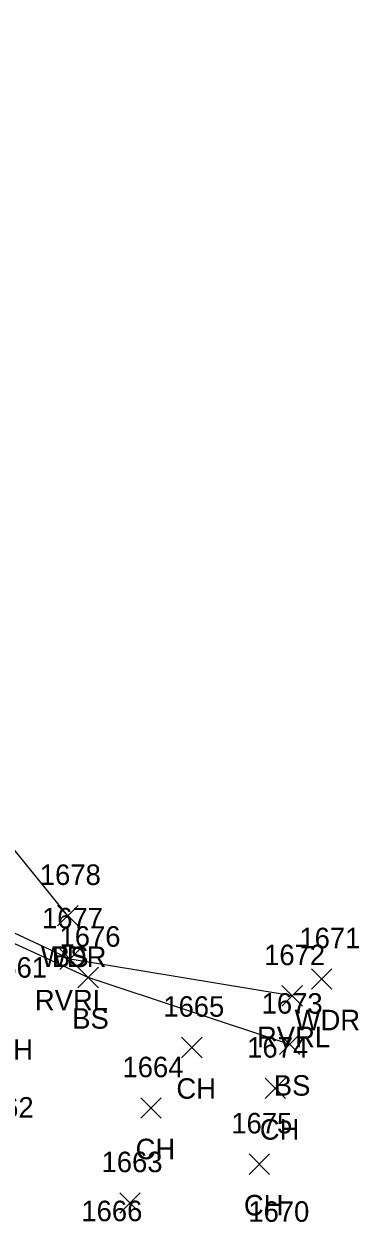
# Model space of a CAD drawing. Extents: x 1537342 to 1542195, y 163002 to 168596.
# Drawn here: x 1541938.8 to 1541971.5, y 163352.8 to 163469.6 of the extents above; entities that cross this region are included whole.
import ezdxf

# ---------------------------------------------------------------- set-up
doc = ezdxf.new("R2010")
doc.units = 0
for name, color, linetype in [('L_A', 7, 'Continuous'), ('L_I', 7, 'Continuous'), ('L_TIC', 7, 'Continuous'), ('LAWE', 7, 'Continuous'), ('LELB', 7, 'Continuous')]:
    doc.layers.add(name, color=color, linetype=linetype)

msp = doc.modelspace()

# ---------------------------------------------------------------- linework, layer by layer
at = {"layer": 'L_TIC'}
for points in [[(1541942.1, 163381.66), (1541944.1, 163383.66)], [(1541944.1, 163381.66), (1541942.1, 163383.66)], [(1541942.1, 163381.66), (1541944.1, 163383.66)], [(1541944.1, 163381.66), (1541942.1, 163383.66)], [(1541942.31, 163377.43), (1541944.31, 163379.43)], [(1541944.31, 163377.43), (1541942.31, 163379.43)], [(1541944.07, 163375.64), (1541946.07, 163377.64)], [(1541946.07, 163375.64), (1541944.07, 163377.64)], [(1541966.84, 163375.49), (1541968.84, 163377.49)], [(1541968.84, 163375.49), (1541966.84, 163377.49)], [(1541963.97, 163373.84), (1541965.97, 163375.84)], [(1541965.97, 163373.84), (1541963.97, 163375.84)], [(1541963.73, 163369.11), (1541965.73, 163371.11)], [(1541965.73, 163369.11), (1541963.73, 163371.11)], [(1541954.19, 163368.81), (1541956.19, 163370.81)], [(1541956.19, 163368.81), (1541954.19, 163370.81)], [(1541962.32, 163364.82), (1541964.32, 163366.82)], [(1541964.32, 163364.82), (1541962.32, 163366.82)], [(1541950.21, 163362.91), (1541952.21, 163364.91)], [(1541952.21, 163362.91), (1541950.21, 163364.91)], [(1541960.77, 163357.43), (1541962.77, 163359.43)], [(1541962.77, 163357.43), (1541960.77, 163359.43)], [(1541948.16, 163353.65), (1541950.16, 163355.65)], [(1541950.16, 163353.65), (1541948.16, 163355.65)]]:
    msp.add_lwpolyline(points, dxfattribs=at)
at = {"layer": 'LAWE'}
msp.add_lwpolyline([(1541964.97, 163374.84), (1541943.31, 163378.43), (1541921.03, 163388.83), (1541900.78, 163403.75), (1541870.95, 163416.96), (1541842.26, 163431.79), (1541812.16, 163446.74), (1541779.01, 163455.02), (1541742.66, 163469.64)], dxfattribs=at)
at = {"layer": 'LELB'}
for points in [[(1541964.73, 163370.11), (1541945.07, 163376.64), (1541920.27, 163388.01), (1541900.01, 163403.43), (1541870.81, 163416.57), (1541842.39, 163430.68), (1541811.88, 163446.01), (1541778.73, 163450.23), (1541740.6, 163464.39)], [(1541943.1, 163382.66), (1541929.91, 163398.91), (1541907.78, 163419.17), (1541886.16, 163442.24)]]:
    msp.add_lwpolyline(points, dxfattribs=at)

# ---------------------------------------------------------------- texts
at = {"layer": 'L_A'}
for s, p in [('WDR', (1541940.47, 163377.66)), ('BS', (1541941.54, 163377.66)), ('RVRL', (1541939.88, 163373.43)), ('BS', (1541943.52, 163371.64)), ('WDR', (1541965.21, 163371.49)), ('RVRL', (1541961.54, 163369.84)), ('CH', (1541935.83, 163368.62)), ('CH', (1541953.68, 163364.81)), ('BS', (1541963.18, 163365.11)), ('CH', (1541961.81, 163360.82)), ('CH', (1541949.7, 163358.91)), ('CH', (1541960.26, 163353.43))]:
    msp.add_text(s, height=2, dxfattribs=at).set_placement(p)
at = {"layer": 'L_I'}
for s, p in [('1678', (1541940.36, 163385.66)), ('1678', (1541940.36, 163385.66)), ('1677', (1541940.57, 163381.43)), ('1676', (1541942.28, 163379.64)), ('1671', (1541965.67, 163379.49)), ('1672', (1541962.23, 163377.84)), ('1661', (1541935.12, 163376.62)), ('1665', (1541952.4, 163372.81)), ('1673', (1541961.99, 163373.11)), ('1674', (1541960.58, 163368.82)), ('1664', (1541948.42, 163366.91)), ('1662', (1541933.81, 163362.97)), ('1675', (1541959.03, 163361.43)), ('1663', (1541946.38, 163357.65)), ('1666', (1541944.41, 163352.87)), ('1670', (1541960.69, 163352.81))]:
    msp.add_text(s, height=2, dxfattribs=at).set_placement(p)

doc.saveas('drawing.dxf')
